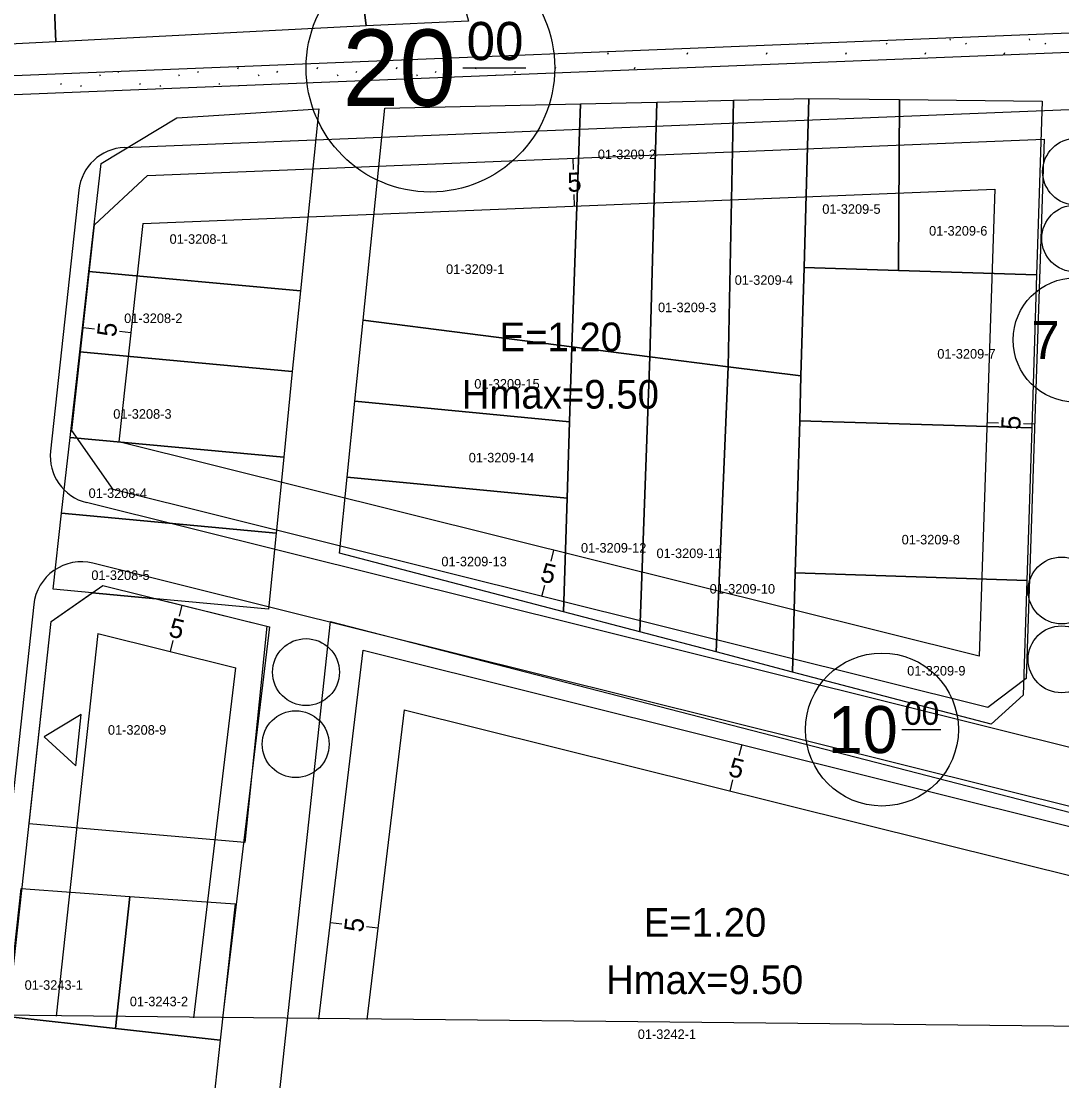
# Model space of a CAD drawing. Extents: x 419396 to 421519, y 4453567 to 4456767.
# Drawn here: x 420734.2 to 420843, y 4454304 to 4454414.9 of the extents above; entities that cross this region are included whole.
import ezdxf

# ---------------------------------------------------------------- set-up
doc = ezdxf.new("R2010")
doc.units = 0
for name, color, linetype in [('0_KADASTRO', 7, 'Continuous'), ('Level 16', 7, 'Continuous'), ('Level 20', 7, 'Continuous'), ('Level 29', 7, 'Continuous'), ('Level 30', 7, 'Continuous'), ('Level 41', 7, 'Continuous'), ('Level 55', 7, 'Continuous'), ('Level 58', 7, 'Continuous'), ('Level 62', 7, 'Continuous'), ('Y_Lejant', 7, 'Continuous')]:
    doc.layers.add(name, color=color, linetype=linetype)

msp = doc.modelspace()

# ---------------------------------------------------------------- linework, layer by layer
at = {"layer": '0_KADASTRO'}
for points in [[(420700.02, 4454589.2), (420728.3, 4454590.91), (420741.39, 4454490.48), (420755.01, 4454491.22), (420760.8, 4454491.14), (420770.28, 4454414.41), (420737.81, 4454412.75), (420737.32, 4454424.69), (420737.17, 4454427.02), (420736.8, 4454440.33), (420736.79, 4454443.57), (420736.53, 4454449.88), (420735.04, 4454485.63), (420707.81, 4454489.19), (420700.8, 4454489.5)], [(420760.8, 4454491.14), (420768.78, 4454490.27), (420778.15, 4454431.65), (420779.07, 4454425.7), (420779.87, 4454421.02), (420780.78, 4454415.68), (420780.99, 4454414.91), (420770.28, 4454414.41)], [(420704.87, 4454428.71), (420705.73, 4454450.25), (420706.62, 4454472.48), (420706.8, 4454476.84), (420707.02, 4454479.58), (420707.81, 4454489.19), (420735.04, 4454485.63), (420736.53, 4454449.88), (420736.79, 4454443.57), (420736.8, 4454440.33), (420737.17, 4454427.02), (420737.32, 4454424.69), (420737.81, 4454412.75), (420705.15, 4454411.12), (420705.05, 4454417.5)], [(420799.95, 4454379.8), (420800.68, 4454406.44), (420808.68, 4454406.63), (420808.13, 4454378.75)], [(420808.13, 4454378.75), (420808.68, 4454406.63), (420816.57, 4454406.81), (420816.07, 4454389.15), (420815.75, 4454377.79)], [(420816.07, 4454389.15), (420816.57, 4454406.81), (420826.07, 4454406.7), (420825.95, 4454388.83)], [(420825.95, 4454388.83), (420826.07, 4454406.7), (420840.98, 4454406.53), (420840.4, 4454388.36)], [(420741.27, 4454388.72), (420742.54, 4454400), (420750.46, 4454404.8), (420765.33, 4454405.74), (420763.41, 4454386.69)], [(420769.95, 4454383.61), (420772.21, 4454405.82), (420792.69, 4454406.27), (420791.77, 4454380.84)], [(420791.77, 4454380.84), (420792.69, 4454406.27), (420800.68, 4454406.44), (420799.95, 4454379.8)], [(420815.62, 4454373.1), (420815.75, 4454377.79), (420816.07, 4454389.15), (420825.95, 4454388.83), (420840.4, 4454388.36), (420839.88, 4454372.37)], [(420740.34, 4454380.3), (420741.27, 4454388.72), (420763.41, 4454386.69), (420762.55, 4454378.24)], [(420769.1, 4454375.15), (420769.95, 4454383.61), (420791.77, 4454380.84), (420791.54, 4454372.98)], [(420739.33, 4454371.34), (420740.34, 4454380.3), (420762.55, 4454378.24), (420761.65, 4454369.29)], [(420790.92, 4454353.1), (420791.28, 4454364.99), (420791.54, 4454372.98), (420791.77, 4454380.84), (420799.95, 4454379.8), (420798.9, 4454351)], [(420798.9, 4454351), (420799.95, 4454379.8), (420808.13, 4454378.75), (420806.88, 4454348.91)], [(420806.88, 4454348.91), (420808.13, 4454378.75), (420815.75, 4454377.79), (420815.62, 4454373.1), (420815.15, 4454357.18), (420814.85, 4454346.81)], [(420768.28, 4454367.2), (420769.1, 4454375.15), (420791.54, 4454372.98), (420791.28, 4454364.99)], [(420815.15, 4454357.18), (420815.62, 4454373.1), (420839.88, 4454372.37), (420839.37, 4454356.39)], [(420738.42, 4454363.42), (420739.33, 4454371.34), (420761.65, 4454369.29), (420760.85, 4454361.33)], [(420767.47, 4454359.24), (420768.28, 4454367.2), (420791.28, 4454364.99), (420790.92, 4454353.1)], [(420737.55, 4454355.48), (420738.42, 4454363.42), (420760.85, 4454361.33), (420760.05, 4454353.37), (420748.32, 4454354.47), (420741.62, 4454355.1)], [(420814.85, 4454346.81), (420815.15, 4454357.18), (420839.37, 4454356.39), (420838.99, 4454344.4), (420835.64, 4454341.37)], [(420735.02, 4454330.92), (420737.33, 4454352.11), (420741.62, 4454355.1), (420748.32, 4454354.47), (420759.87, 4454351.59), (420759.24, 4454345.41), (420757.58, 4454328.99), (420746.62, 4454329.93)], [(420760.42, 4454295.25), (420766.53, 4454352.09), (420860.16, 4454327.91), (420861.03, 4454322.83), (420850.45, 4454305.8), (420831.03, 4454272.79)], [(420732.74, 4454310.75), (420734.2, 4454324.17), (420745.57, 4454323.32), (420744.07, 4454309.5)], [(420744.07, 4454309.5), (420745.57, 4454323.32), (420756.56, 4454322.54), (420755.01, 4454308.29)], [(420731.89, 4454302.79), (420732.74, 4454310.75), (420744.07, 4454309.5), (420755.01, 4454308.29), (420754.14, 4454300.27)]]:
    msp.add_lwpolyline(points, close=True, dxfattribs=at)
at = {"layer": 'Level 16'}
for p, q in [((420740.48, 4454342.35), (420736.61, 4454340.04)), ((420739.91, 4454336.98), (420740.48, 4454342.35)), ((420736.61, 4454340.04), (420739.91, 4454336.98))]:
    msp.add_line(p, q, dxfattribs=at)
at = {"layer": 'Level 20'}
for p, q in [((420791.88, 4454400.57), (420791.92, 4454399.37)), ((420746.9, 4454393.75), (420836.03, 4454397.34)), ((420792.08, 4454395.57), (420792.03, 4454396.77)), ((420836.03, 4454397.34), (420834.4, 4454348.47)), ((420746.9, 4454393.75), (420744.41, 4454370.91)), ((420740.68, 4454382.84), (420741.87, 4454382.71)), ((420745.65, 4454382.3), (420744.46, 4454382.43)), ((420835.21, 4454372.91), (420836.41, 4454372.87)), ((420840.21, 4454372.74), (420839.01, 4454372.78)), ((420834.4, 4454348.47), (420744.41, 4454370.91)), ((420789.87, 4454359.57), (420789.58, 4454358.41)), ((420788.66, 4454354.72), (420788.96, 4454355.88)), ((420751, 4454353.8), (420750.71, 4454352.64)), ((420742.22, 4454350.84), (420737.85, 4454310.79)), ((420742.22, 4454350.84), (420756.64, 4454347.24)), ((420749.79, 4454348.95), (420750.08, 4454350.12)), ((420752.25, 4454310.64), (420756.64, 4454347.24)), ((420774.24, 4454342.86), (420770.35, 4454310.45)), ((420774.24, 4454342.86), (420855.58, 4454322.58)), ((420809.55, 4454339.21), (420809.26, 4454338.04)), ((420808.34, 4454334.36), (420808.63, 4454335.52)), ((420766.53, 4454320.59), (420767.73, 4454320.45)), ((420771.5, 4454320), (420770.31, 4454320.14))]:
    msp.add_line(p, q, dxfattribs=at)
at = {"layer": 'Level 29'}
for p, q in [((420747.39, 4454398.77), (420841.2, 4454402.55)), ((420841.2, 4454402.55), (420839.32, 4454346.12)), ((420741.85, 4454393.6), (420747.39, 4454398.77)), ((420739.5, 4454372.08), (420741.85, 4454393.6)), ((420743.81, 4454365.9), (420739.5, 4454372.08)), ((420835.31, 4454343.09), (420743.81, 4454365.9)), ((420737.33, 4454352.11), (420742.72, 4454355.87)), ((420742.72, 4454355.87), (420760.17, 4454351.52)), ((420732.83, 4454310.84), (420737.33, 4454352.11)), ((420760.17, 4454351.52), (420755.26, 4454310.61)), ((420765.32, 4454310.5), (420769.95, 4454349.08)), ((420769.95, 4454349.08), (420849.15, 4454329.33)), ((420839.32, 4454346.12), (420835.31, 4454343.09))]:
    msp.add_line(p, q, dxfattribs=at)
at = {"layer": 'Level 41'}
for p, q in [((420816.4, 4454412.57), (420816.45, 4454412.49)), ((420824.67, 4454412.6), (420824.74, 4454412.49)), ((420831.33, 4454413.07), (420831.35, 4454412.91)), ((420832.96, 4454412.6), (420833.03, 4454412.49)), ((420839.63, 4454413.07), (420839.64, 4454412.91)), ((420841.26, 4454412.6), (420841.33, 4454412.49)), ((420795.55, 4454411.46), (420795.63, 4454411.62)), ((420803.85, 4454411.46), (420803.92, 4454411.62)), ((420812.14, 4454411.46), (420812.21, 4454411.62)), ((420820.43, 4454411.46), (420820.51, 4454411.62)), ((420828.73, 4454411.46), (420828.8, 4454411.62)), ((420837.02, 4454411.46), (420837.09, 4454411.62)), ((420756.86, 4454409.93), (420756.93, 4454410.09)), ((420765.15, 4454409.93), (420765.22, 4454410.09)), ((420773.45, 4454409.93), (420773.52, 4454410.09)), ((420781.74, 4454409.93), (420781.81, 4454410.09)), ((420790.03, 4454409.93), (420790.1, 4454410.09)), ((420798.33, 4454409.93), (420798.4, 4454410.09)), ((420742.37, 4454409.31), (420742.44, 4454409.2)), ((420744.36, 4454409.52), (420744.42, 4454409.67)), ((420750.66, 4454409.31), (420750.73, 4454409.2)), ((420752.65, 4454409.52), (420752.72, 4454409.68)), ((420758.96, 4454409.31), (420759.03, 4454409.2)), ((420760.94, 4454409.52), (420761.02, 4454409.68)), ((420767.25, 4454409.31), (420767.32, 4454409.2)), ((420769.24, 4454409.52), (420769.31, 4454409.68)), ((420775.54, 4454409.31), (420775.61, 4454409.2)), ((420777.53, 4454409.52), (420777.6, 4454409.68)), ((420783.84, 4454409.31), (420783.87, 4454409.26)), ((420785.82, 4454409.52), (420785.89, 4454409.68)), ((420794.18, 4454409.67), (420794.19, 4454409.68)), ((420738.29, 4454408.38), (420738.36, 4454408.27)), ((420740.38, 4454408.19), (420740.46, 4454408.08)), ((420746.58, 4454408.38), (420746.65, 4454408.27)), ((420748.68, 4454408.19), (420748.75, 4454408.08)), ((420754.87, 4454408.38), (420754.94, 4454408.27)), ((420756.97, 4454408.19), (420756.98, 4454408.17))]:
    msp.add_line(p, q, dxfattribs=at)
at = {"layer": 'Level 55'}
for centre in [(420844.53, 4454399.16), (420844.44, 4454392.17), (420843.01, 4454355.34), (420843.01, 4454348.14), (420763.98, 4454346.8), (420762.9, 4454339.26)]:
    msp.add_circle(centre, 3.5, dxfattribs=at)
at = {"layer": 'Level 58'}
for p, q in [((420780.38, 4454410.03), (420786.98, 4454410.03)), ((420826.31, 4454340.79), (420830.37, 4454340.79))]:
    msp.add_line(p, q, dxfattribs=at)
for centre, radius in [((420776.99, 4454410.03), 13), ((420844.44, 4454381.55), 6.5), ((420824.22, 4454340.79), 8)]:
    msp.add_circle(centre, radius, dxfattribs=at)
at = {"layer": 'Level 62'}
for p, q in [((420728.16, 4454409.01), (420871.12, 4454414.77)), ((420728.14, 4454407.01), (420875.73, 4454412.96)), ((420745, 4454401.68), (420875.59, 4454406.95)), ((420740.23, 4454397.23), (420737.26, 4454369.93)), ((420851.09, 4454337.1), (420741.02, 4454364.54)), ((420849.64, 4454331.28), (420741.69, 4454358.19)), ((420735.51, 4454353.88), (420730.82, 4454310.86))]:
    msp.add_line(p, q, dxfattribs=at)
for centre, start, end in [((420745.2, 4454396.69), 92.3077, 173.779), ((420742.23, 4454369.39), 173.779, 256.002), ((420740.48, 4454353.34), 76.002, 173.779)]:
    msp.add_arc(centre, 5, start, end, dxfattribs=at)
at = {"layer": 'Y_Lejant'}
msp.add_lwpolyline([(420209.76, 4455704.6), (421518.56, 4455690.86), (421518.56, 4454302.65), (420195.09, 4454316.54)], close=True, dxfattribs=at)

# ---------------------------------------------------------------- texts
at = {"layer": '0_KADASTRO'}
for s, p in [('01-3209-2', (420794.5, 4454400.47)), ('01-3209-5', (420817.98, 4454394.75)), ('01-3209-6', (420829.15, 4454392.47)), ('01-3208-1', (420749.71, 4454391.61)), ('01-3209-1', (420778.63, 4454388.46)), ('01-3209-4', (420808.82, 4454387.32)), ('01-3209-3', (420800.8, 4454384.46)), ('01-3208-2', (420744.96, 4454383.32)), ('01-3209-7', (420830.01, 4454379.6)), ('01-3209-15', (420781.58, 4454376.46)), ('01-3208-3', (420743.82, 4454373.31)), ('01-3209-14', (420781, 4454368.74)), ('01-3208-4', (420741.24, 4454365.02)), ('01-3209-8', (420826.28, 4454360.16)), ('01-3209-12', (420792.74, 4454359.3)), ('01-3209-13', (420778.14, 4454357.87)), ('01-3209-11', (420800.64, 4454358.73)), ('01-3208-5', (420741.53, 4454356.44)), ('01-3209-10', (420806.2, 4454355.01)), ('01-3209-9', (420826.86, 4454346.44)), ('01-3208-9', (420743.26, 4454340.25)), ('01-3243-1', (420734.55, 4454313.56)), ('01-3243-2', (420745.55, 4454311.84)), ('01-3242-1', (420798.68, 4454308.41))]:
    msp.add_text(s, height=1, dxfattribs=at).set_placement(p)
at = {"layer": 'Level 20'}
for rotation, p in [(2.3077, (420791.35, 4454397.04)), (83.779, (420744.09, 4454381.8)), (88.0908, (420838.69, 4454372.12)), (346.0019, (420788.38, 4454356.34)), (346.0019, (420749.51, 4454350.57)), (346.0019, (420808.06, 4454335.97)), (83.1572, (420769.93, 4454319.51))]:
    msp.add_text('5', height=2, rotation=rotation, dxfattribs=at).set_placement(p)
at = {"layer": 'Level 30'}
for s, p in [('E=1.20', (420784.21, 4454380.37)), ('Hmax=9.50', (420780.27, 4454374.37)), ('E=1.20', (420799.3, 4454319.11)), ('Hmax=9.50', (420795.36, 4454313.11))]:
    msp.add_text(s, height=3, dxfattribs=at).set_placement(p)
at = {"layer": 'Level 58'}
for s, height, p in [('00', 3.997, (420780.78, 4454410.83)), ('20', 7.993, (420767.79, 4454406.04)), ('7', 4, (420839.84, 4454379.55)), ('10', 4.919, (420818.56, 4454338.33)), ('00', 2.46, (420826.55, 4454341.28))]:
    msp.add_text(s, height=height, dxfattribs=at).set_placement(p)

doc.saveas('drawing.dxf')
